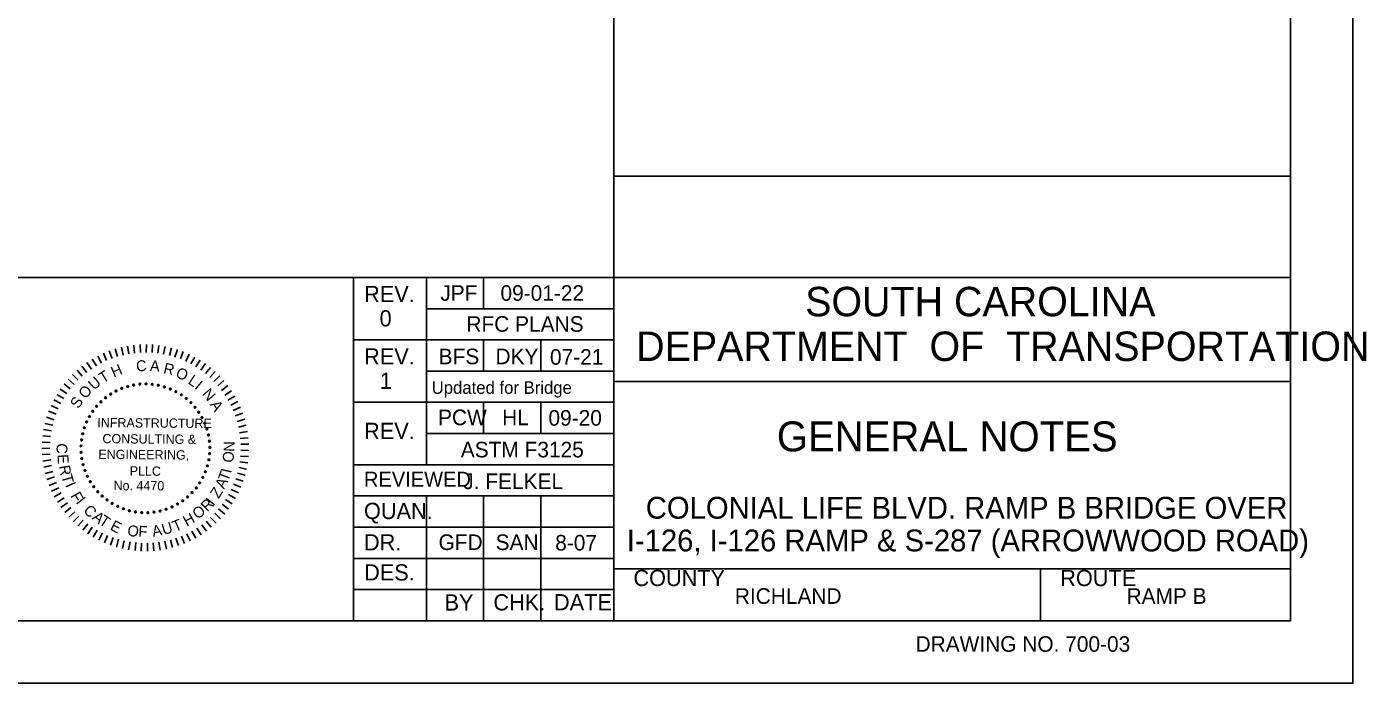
# Model space of a CAD drawing. Extents: x -1.3 to 34.8, y 0.8 to 22.8.
# Drawn here: x 24.06 to 34.78, y 0.82 to 6.08 of the extents above; entities that cross this region are included whole.
import ezdxf

# ---------------------------------------------------------------- set-up
doc = ezdxf.new("R2010")
doc.units = 0
for name, color, linetype in [('BR_BORDER LINES', 7, 'Continuous'), ('BR_TEXT', 7, 'Continuous'), ('Level 31', 7, 'Continuous')]:
    doc.layers.add(name, color=color, linetype=linetype)

msp = doc.modelspace()

# ---------------------------------------------------------------- linework, layer by layer
at = {"layer": 'BR_BORDER LINES'}
for p, q in [((34.177, 1.318), (34.177, 22.318)), ((28.76, 1.318), (28.76, 6.595)), ((28.76, 4.88), (34.177, 4.88)), ((21.311, 4.068), (26.676, 4.068)), ((26.676, 1.318), (26.676, 4.068)), ((26.676, 4.068), (34.177, 4.068)), ((27.26, 4.068), (27.26, 2.568)), ((27.718, 3.818), (27.718, 4.068)), ((27.26, 3.818), (28.76, 3.818)), ((26.676, 3.568), (28.76, 3.568)), ((27.718, 3.318), (27.718, 3.568)), ((28.176, 3.318), (28.176, 3.568)), ((27.26, 3.318), (28.76, 3.318)), ((28.76, 3.235), (28.76, 3.235)), ((28.76, 3.235), (34.177, 3.235)), ((26.676, 3.068), (28.76, 3.068)), ((27.718, 2.818), (27.718, 3.068)), ((28.176, 2.818), (28.176, 3.068)), ((27.26, 2.818), (28.76, 2.818)), ((26.676, 2.568), (28.76, 2.568)), ((26.676, 2.318), (28.76, 2.318)), ((27.26, 2.318), (27.26, 1.318)), ((27.718, 2.318), (27.718, 1.318)), ((28.176, 2.318), (28.176, 1.318)), ((26.676, 2.068), (28.76, 2.068)), ((26.676, 1.818), (28.76, 1.818)), ((28.76, 1.735), (34.177, 1.735)), ((28.857, 1.735), (34.177, 1.735)), ((32.177, 1.318), (32.177, 1.735)), ((26.676, 1.568), (28.76, 1.568)), ((0.511, 1.318), (34.177, 1.318))]:
    msp.add_line(p, q, dxfattribs=at)
at = {"layer": 'BR_TEXT'}
for p, q in [((24.629, 3.439), (24.658, 3.382)), ((24.674, 3.461), (24.7, 3.402)), ((24.721, 3.48), (24.743, 3.42)), ((24.769, 3.496), (24.788, 3.435)), ((24.818, 3.509), (24.832, 3.447)), ((24.867, 3.519), (24.878, 3.456)), ((24.917, 3.526), (24.924, 3.463)), ((24.967, 3.531), (24.971, 3.467)), ((25.018, 3.532), (25.017, 3.468)), ((25.068, 3.53), (25.064, 3.466)), ((25.118, 3.524), (25.11, 3.461)), ((25.168, 3.516), (25.156, 3.454)), ((25.218, 3.505), (25.202, 3.444)), ((25.266, 3.491), (25.246, 3.43)), ((25.313, 3.474), (25.29, 3.415)), ((25.36, 3.454), (25.333, 3.396)), ((24.463, 3.325), (24.505, 3.277)), ((24.501, 3.357), (24.541, 3.307)), ((24.542, 3.387), (24.578, 3.334)), ((24.585, 3.414), (24.618, 3.359)), ((25.405, 3.431), (25.375, 3.375)), ((25.449, 3.406), (25.415, 3.352)), ((25.491, 3.378), (25.454, 3.326)), ((25.531, 3.347), (25.491, 3.298)), ((24.391, 3.254), (24.439, 3.211)), ((24.426, 3.29), (24.471, 3.245)), ((25.569, 3.314), (25.526, 3.267)), ((25.605, 3.279), (25.559, 3.235)), ((25.639, 3.242), (25.591, 3.2)), ((24.301, 3.132), (24.356, 3.099)), ((24.329, 3.174), (24.381, 3.138)), ((24.359, 3.215), (24.409, 3.176)), ((25.671, 3.202), (25.62, 3.164)), ((25.7, 3.161), (25.647, 3.126)), ((25.726, 3.118), (25.671, 3.086)), ((24.255, 3.042), (24.313, 3.016)), ((24.277, 3.088), (24.333, 3.058)), ((25.75, 3.074), (25.693, 3.045)), ((25.772, 3.028), (25.713, 3.003)), ((24.206, 2.899), (24.268, 2.884)), ((24.219, 2.948), (24.28, 2.929)), ((24.235, 2.996), (24.295, 2.973)), ((25.79, 2.981), (25.73, 2.96)), ((25.805, 2.933), (25.744, 2.915)), ((24.188, 2.8), (24.251, 2.793)), ((24.195, 2.85), (24.258, 2.839)), ((25.818, 2.884), (25.756, 2.87)), ((25.827, 2.834), (25.764, 2.824)), ((24.182, 2.699), (24.246, 2.7)), ((24.184, 2.75), (24.247, 2.746)), ((25.834, 2.784), (25.77, 2.778)), ((25.837, 2.734), (25.773, 2.732)), ((25.837, 2.683), (25.774, 2.685)), ((24.184, 2.649), (24.248, 2.653)), ((24.189, 2.598), (24.252, 2.607)), ((25.829, 2.583), (25.766, 2.592)), ((25.835, 2.633), (25.771, 2.638)), ((24.197, 2.549), (24.259, 2.561)), ((24.208, 2.499), (24.27, 2.515)), ((24.222, 2.451), (24.282, 2.47)), ((25.808, 2.484), (25.747, 2.501)), ((25.82, 2.533), (25.758, 2.546)), ((24.239, 2.403), (24.298, 2.426)), ((24.259, 2.357), (24.316, 2.384)), ((25.755, 2.343), (25.697, 2.37)), ((25.775, 2.389), (25.716, 2.413)), ((25.793, 2.436), (25.733, 2.456)), ((24.281, 2.312), (24.337, 2.342)), ((24.306, 2.268), (24.36, 2.302)), ((24.334, 2.226), (24.386, 2.263)), ((25.705, 2.255), (25.652, 2.289)), ((25.731, 2.298), (25.676, 2.329)), ((24.365, 2.186), (24.414, 2.225)), ((24.397, 2.147), (24.445, 2.19)), ((24.433, 2.111), (24.477, 2.157)), ((25.576, 2.1), (25.532, 2.146)), ((25.612, 2.136), (25.565, 2.179)), ((25.645, 2.173), (25.596, 2.214)), ((25.676, 2.213), (25.625, 2.251)), ((24.47, 2.077), (24.511, 2.125)), ((24.509, 2.045), (24.548, 2.096)), ((24.55, 2.016), (24.585, 2.069)), ((24.593, 1.989), (24.625, 2.044)), ((25.457, 2.007), (25.422, 2.061)), ((25.498, 2.036), (25.461, 2.087)), ((25.538, 2.067), (25.497, 2.116)), ((24.637, 1.965), (24.666, 2.022)), ((24.683, 1.943), (24.708, 2.002)), ((24.73, 1.925), (24.751, 1.985)), ((24.778, 1.909), (24.796, 1.971)), ((24.827, 1.897), (24.841, 1.959)), ((24.876, 1.887), (24.887, 1.95)), ((24.927, 1.88), (24.933, 1.944)), ((24.977, 1.877), (24.979, 1.94)), ((25.027, 1.876), (25.026, 1.94)), ((25.078, 1.879), (25.072, 1.942)), ((25.128, 1.885), (25.119, 1.948)), ((25.178, 1.893), (25.165, 1.956)), ((25.227, 1.905), (25.21, 1.967)), ((25.275, 1.92), (25.255, 1.98)), ((25.322, 1.937), (25.298, 1.996)), ((25.369, 1.958), (25.341, 2.015)), ((25.413, 1.981), (25.382, 2.037))]:
    msp.add_line(p, q, dxfattribs=at)
for centre, start, end in [((24.966, 3.214), 5.0653, 185.0653), ((25.015, 3.215), 359.5268, 179.5268), ((25.065, 3.213), 353.9884, 173.9884), ((24.691, 3.105), 38.2961, 218.2961), ((24.732, 3.134), 32.7576, 212.7576), ((24.732, 3.134), 212.7576, 32.7576), ((24.775, 3.159), 27.2191, 207.2191), ((24.775, 3.159), 207.2191, 27.2191), ((24.821, 3.179), 21.6807, 201.6807), ((24.821, 3.179), 201.6807, 21.6807), ((24.868, 3.195), 16.1422, 196.1422), ((24.868, 3.195), 196.1422, 16.1422), ((24.916, 3.207), 10.6038, 190.6038), ((24.916, 3.207), 190.6038, 10.6038), ((24.966, 3.214), 185.0653, 5.0653), ((25.015, 3.215), 179.5268, 359.5268), ((25.065, 3.213), 173.9884, 353.9884), ((25.114, 3.205), 348.4499, 168.4499), ((25.114, 3.205), 168.4499, 348.4499), ((25.163, 3.192), 342.9114, 162.9114), ((25.163, 3.192), 162.9114, 342.9114), ((25.209, 3.175), 157.373, 337.373), ((25.209, 3.175), 337.373, 157.373), ((25.254, 3.154), 151.8345, 331.8345), ((25.254, 3.154), 331.8345, 151.8345), ((25.297, 3.128), 146.2961, 326.2961), ((25.297, 3.128), 326.2961, 146.2961), ((24.589, 2.997), 54.9114, 234.9114), ((24.589, 2.997), 234.9114, 54.9114), ((24.619, 3.036), 49.373, 229.373), ((24.619, 3.036), 229.373, 49.373), ((24.654, 3.072), 43.8345, 223.8345), ((24.654, 3.072), 223.8345, 43.8345), ((24.691, 3.105), 218.2961, 38.2961), ((25.337, 3.099), 140.7576, 320.7576), ((25.337, 3.099), 320.7576, 140.7576), ((25.374, 3.065), 135.2191, 315.2191), ((25.374, 3.065), 315.2191, 135.2191), ((25.408, 3.028), 129.6807, 309.6807), ((25.408, 3.028), 309.6807, 129.6807), ((24.539, 2.911), 65.9884, 245.9884), ((24.539, 2.911), 245.9884, 65.9884), ((24.562, 2.955), 60.4499, 240.4499), ((24.562, 2.955), 240.4499, 60.4499), ((25.437, 2.988), 124.1422, 304.1422), ((25.437, 2.988), 304.1422, 124.1422), ((25.463, 2.946), 118.6038, 298.6038), ((25.463, 2.946), 298.6038, 118.6038), ((25.485, 2.901), 113.0653, 293.0653), ((25.485, 2.901), 293.0653, 113.0653), ((24.508, 2.816), 77.0653, 257.0653), ((24.508, 2.816), 257.0653, 77.0653), ((24.521, 2.864), 71.5268, 251.5268), ((24.521, 2.864), 251.5268, 71.5268), ((25.502, 2.854), 107.5268, 287.5268), ((25.502, 2.854), 287.5268, 107.5268), ((25.515, 2.806), 101.9884, 281.9884), ((25.515, 2.806), 281.9884, 101.9884), ((24.495, 2.718), 88.1422, 268.1422), ((24.499, 2.767), 82.6038, 262.6038), ((24.495, 2.718), 268.1422, 88.1422), ((24.499, 2.767), 262.6038, 82.6038), ((25.523, 2.757), 96.4499, 276.4499), ((25.526, 2.707), 90.9114, 270.9114), ((25.523, 2.757), 276.4499, 96.4499), ((25.526, 2.707), 270.9114, 90.9114), ((24.495, 2.668), 93.6807, 273.6807), ((24.501, 2.618), 99.2191, 279.2191), ((24.495, 2.668), 273.6807, 93.6807), ((24.501, 2.618), 279.2191, 99.2191), ((24.511, 2.569), 104.7576, 284.7576), ((24.511, 2.569), 284.7576, 104.7576), ((25.518, 2.608), 79.8345, 259.8345), ((25.518, 2.608), 259.8345, 79.8345), ((25.524, 2.657), 85.373, 265.373), ((25.524, 2.657), 265.373, 85.373), ((24.526, 2.522), 110.2961, 290.2961), ((24.526, 2.522), 290.2961, 110.2961), ((24.545, 2.476), 115.8345, 295.8345), ((24.545, 2.476), 295.8345, 115.8345), ((25.47, 2.466), 63.2191, 243.2191), ((25.47, 2.466), 243.2191, 63.2191), ((25.49, 2.512), 68.7576, 248.7576), ((25.49, 2.512), 248.7576, 68.7576), ((25.506, 2.559), 74.2961, 254.2961), ((25.506, 2.559), 254.2961, 74.2961), ((24.569, 2.432), 121.373, 301.373), ((24.569, 2.432), 301.373, 121.373), ((24.597, 2.391), 126.9114, 306.9114), ((24.597, 2.391), 306.9114, 126.9114), ((24.629, 2.352), 312.4499, 132.4499), ((25.417, 2.382), 52.1422, 232.1422), ((25.417, 2.382), 232.1422, 52.1422), ((25.445, 2.423), 57.6807, 237.6807), ((25.445, 2.423), 237.6807, 57.6807), ((24.629, 2.352), 132.4499, 312.4499), ((24.664, 2.317), 137.9884, 317.9884), ((24.664, 2.317), 317.9884, 137.9884), ((24.703, 2.286), 143.5268, 323.5268), ((24.703, 2.286), 323.5268, 143.5268), ((24.744, 2.258), 149.0653, 329.0653), ((24.744, 2.258), 329.0653, 149.0653), ((25.267, 2.253), 29.9884, 209.9884), ((25.267, 2.253), 209.9884, 29.9884), ((25.309, 2.279), 35.5268, 215.5268), ((25.309, 2.279), 215.5268, 35.5268), ((25.348, 2.31), 41.0653, 221.0653), ((25.348, 2.31), 221.0653, 41.0653), ((25.384, 2.345), 46.6038, 226.6038), ((25.384, 2.345), 226.6038, 46.6038), ((24.788, 2.234), 154.6038, 334.6038), ((24.788, 2.234), 334.6038, 154.6038), ((24.834, 2.215), 340.1422, 160.1422), ((24.834, 2.215), 160.1422, 340.1422), ((24.882, 2.2), 345.6807, 165.6807), ((24.882, 2.2), 165.6807, 345.6807), ((24.93, 2.19), 351.2191, 171.2191), ((24.93, 2.19), 171.2191, 351.2191), ((24.98, 2.185), 356.7576, 176.7576), ((24.98, 2.185), 176.7576, 356.7576), ((25.03, 2.184), 2.2961, 182.2961), ((25.03, 2.184), 182.2961, 2.2961), ((25.079, 2.189), 7.8345, 187.8345), ((25.079, 2.189), 187.8345, 7.8345), ((25.128, 2.198), 13.373, 193.373), ((25.128, 2.198), 193.373, 13.373), ((25.176, 2.212), 18.9114, 198.9114), ((25.176, 2.212), 198.9114, 18.9114), ((25.223, 2.23), 24.4499, 204.4499), ((25.223, 2.23), 204.4499, 24.4499)]:
    msp.add_arc(centre, 0.00701, start, end, dxfattribs=at)
at = {"layer": 'Level 31'}
msp.add_line((31.468, 2.795), (31.468, 2.795), dxfattribs=at)
msp.add_lwpolyline([(-1.323, 0.818), (34.677, 0.818), (34.677, 22.818), (-1.323, 22.818)], close=True, dxfattribs=at)

# ---------------------------------------------------------------- texts
at = {"layer": 'BR_TEXT'}
for s, height, p in [('REV.', 0.13, (26.761, 3.871)), ('JPF', 0.125, (27.371, 3.881)), ('09-01-22', 0.125, (27.853, 3.881)), ('SOUTH CAROLINA', 0.23587, (30.292, 3.757)), ('0', 0.13, (26.885, 3.676)), ('RFC PLANS', 0.125, (27.58, 3.633)), ('DEPARTMENT  OF  TRANSPORTATION', 0.23587, (28.939, 3.399)), ('REV.', 0.13, (26.761, 3.371)), ('BFS', 0.125, (27.358, 3.373)), ('DKY', 0.125, (27.813, 3.373)), ('07-21', 0.125, (28.249, 3.369)), ('1', 0.13, (26.887, 3.176)), ('Updated for Bridge', 0.1, (27.302, 3.136)), ('PCW', 0.125, (27.353, 2.885)), ('HL', 0.125, (27.866, 2.885)), ('09-20', 0.125, (28.237, 2.881)), ('REV.', 0.13, (26.761, 2.774)), ('GENERAL NOTES', 0.24, (30.065, 2.675)), ('ASTM F3125', 0.125, (27.535, 2.627)), ('REVIEWED', 0.12, (26.76, 2.392)), ('J. FELKEL', 0.125, (27.555, 2.373)), ('QUAN.', 0.13, (26.76, 2.133)), ('COLONIAL LIFE BLVD. RAMP B BRIDGE OVER', 0.175, (29.016, 2.136)), ('I-126, I-126 RAMP & S-287 (ARROWWOOD ROAD) ', 0.175, (28.864, 1.874)), ('DR.', 0.13, (26.76, 1.882)), ('GFD', 0.125, (27.357, 1.885)), ('SAN', 0.125, (27.814, 1.885)), ('8-07', 0.125, (28.291, 1.881)), ('DES.', 0.13, (26.761, 1.641)), ('COUNTY', 0.13, (28.917, 1.596)), ('ROUTE', 0.13, (32.334, 1.596)), ('BY', 0.13, (27.405, 1.4)), ('CHK.', 0.13, (27.796, 1.401)), ('DATE', 0.13, (28.281, 1.402)), ('RICHLAND', 0.125, (29.729, 1.454)), ('RAMP B', 0.125, (32.865, 1.454)), ('DRAWING NO. 700-03', 0.125, (31.176, 1.07))]:
    msp.add_text(s, height=height, dxfattribs=at).set_placement(p)
for s, height, rotation, p in [('T', 0.0872, 31.8182, (24.672, 3.217)), ('H', 0.0872, 22.7882, (24.757, 3.265)), ('C', 0.0872, 4.7281, (24.94, 3.314)), ('A', 0.0872, 355.6981, (25.044, 3.319)), ('R', 0.0872, 346.6681, (25.149, 3.302)), ('O', 0.0872, 337.638, (25.246, 3.272)), ('U', 0.0872, 40.8482, (24.599, 3.161)), ('L', 0.0872, 327.108, (25.345, 3.222)), ('I', 0.0872, 319.578, (25.398, 3.184)), ('S', 0.0872, 58.9083, (24.476, 3.012)), ('O', 0.0872, 49.8782, (24.532, 3.09)), ('N', 0.0872, 310.548, (25.459, 3.133)), ('A', 0.0872, 301.5179, (25.524, 3.051)), ('INFRASTRUCTURE', 0.07477, 359.5268, (24.625, 2.869)), ('CONSULTING &', 0.07477, 359.5268, (24.666, 2.74)), ('C', 0.0872, 267.025, (24.301, 2.742)), ('ENGINEERING,', 0.07477, 359.5268, (24.633, 2.615)), ('N', 0.0872, 89.2085, (25.723, 2.672)), ('E', 0.0872, 273.025, (24.306, 2.65)), ('O', 0.0872, 83.2085, (25.712, 2.581)), ('R', 0.0872, 279.025, (24.319, 2.558)), ('T', 0.0872, 285.025, (24.336, 2.479)), ('PLLC', 0.0748, 359.5268, (24.884, 2.481)), ('T', 0.0872, 69.3954, (25.671, 2.429)), ('I', 0.0872, 77.9093, (25.696, 2.496)), ('I', 0.0872, 293.7713, (24.366, 2.406)), ('No. 4470', 0.0748, 359.5268, (24.755, 2.365)), ('Z', 0.0872, 57.3954, (25.596, 2.292)), ('A', 0.0872, 63.3954, (25.64, 2.368)), ('F', 0.0872, 299.7713, (24.407, 2.32)), ('I', 0.0872, 308.5268, (24.449, 2.266)), ('R', 0.0872, 44.5268, (25.506, 2.187)), ('I', 0.0872, 52.3339, (25.555, 2.234)), ('C', 0.0872, 314.5268, (24.508, 2.196)), ('A', 0.0872, 320.5268, (24.578, 2.137)), ('T', 0.0872, 326.5268, (24.632, 2.099)), ('H', 0.0872, 28.5268, (25.341, 2.071)), ('O', 0.0872, 38.5268, (25.429, 2.127)), ('E', 0.0872, 332.5268, (24.721, 2.051)), ('O', 0.0872, 350.5268, (24.861, 2.002)), ('F', 0.0872, 356.5268, (24.952, 1.993)), ('A', 0.0872, 10.5268, (25.072, 1.991)), ('U', 0.0872, 16.5268, (25.156, 2.005)), ('T', 0.0872, 22.5268, (25.248, 2.029))]:
    msp.add_text(s, height=height, rotation=rotation, dxfattribs=at).set_placement(p)

doc.saveas('drawing.dxf')
